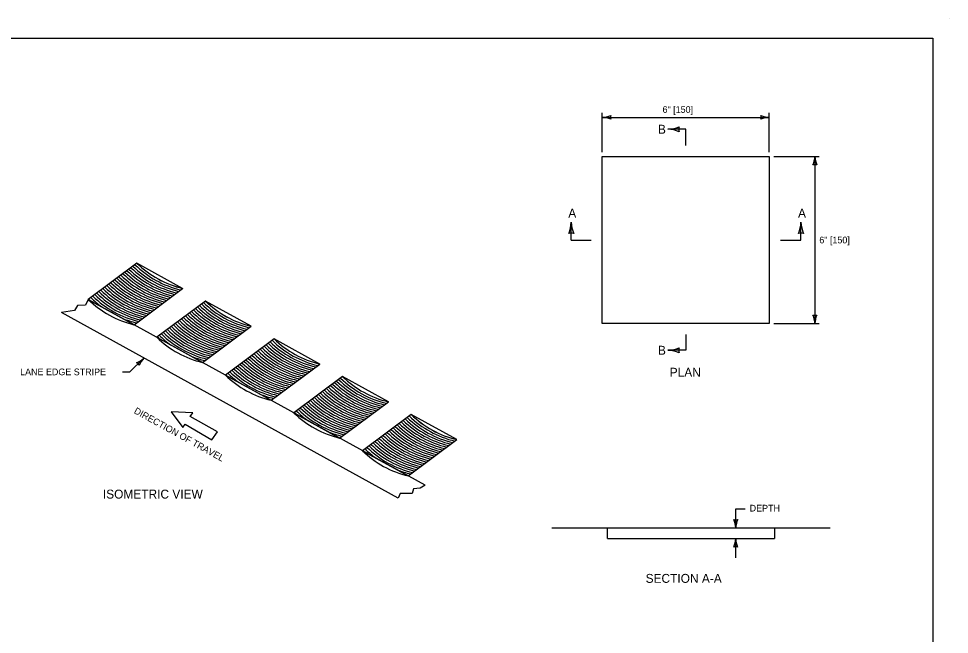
# Model space of a CAD drawing. Extents: x 49991.4 to 50021, y 49987.6 to 50011.4.
# Drawn here: x 50008.54 to 50016.9, y 49993.64 to 49999.18 of the extents above; entities that cross this region are included whole.
import ezdxf

# ---------------------------------------------------------------- set-up
doc = ezdxf.new("R2010")
doc.units = 0
for name, color, linetype in [('Level 1', 7, 'Continuous'), ('Level 2', 7, 'Continuous'), ('Level 3', 7, 'Continuous'), ('Level 4', 7, 'Continuous'), ('Level 6', 7, 'Continuous')]:
    doc.layers.add(name, color=color, linetype=linetype)

msp = doc.modelspace()

# ---------------------------------------------------------------- linework, layer by layer
at = {"layer": 'Level 1'}
for p, q in [((50016.9001, 49999.1756), (50016.9001, 49999.1756)), ((50013.7827, 49996.4368), (50013.7827, 49997.9368)), ((50013.7827, 49997.9368), (50015.2827, 49997.9368)), ((50015.2827, 49997.9368), (50015.2827, 49996.4368)), ((50010.013, 49996.752), (50009.6026, 49996.9783)), ((50009.1656, 49996.6527), (50009.139, 49996.6009)), ((50012.19, 49994.9848), (50009.1656, 49996.6527)), ((50009.0686, 49996.5998), (50009.0413, 49996.5528)), ((50009.139, 49996.6009), (50009.0686, 49996.5998)), ((50010.6291, 49996.4127), (50010.2185, 49996.639)), ((50009.0413, 49996.5528), (50008.9234, 49996.5356)), ((50011.9479, 49994.8676), (50008.9234, 49996.5356)), ((50015.2827, 49996.4368), (50013.7827, 49996.4368)), ((50011.2448, 49996.0731), (50010.8343, 49996.2995)), ((50011.8606, 49995.7335), (50011.4501, 49995.9599)), ((50010.1032, 49995.6332), (50009.9091, 49995.6438)), ((50009.9091, 49995.6438), (50010.0152, 49995.5023)), ((50010.0817, 49995.6015), (50010.1032, 49995.6332)), ((50010.3247, 49995.4635), (50010.0817, 49995.6015)), ((50012.4765, 49995.3939), (50012.066, 49995.6203)), ((50010.0152, 49995.5023), (50010.0363, 49995.5335)), ((50010.0363, 49995.5335), (50010.2756, 49995.3927)), ((50010.2756, 49995.3927), (50010.3247, 49995.4635)), ((50012.19, 49994.9848), (50012.1468, 49994.9565)), ((50011.9674, 49994.9104), (50011.9479, 49994.8676)), ((50012.0758, 49994.9112), (50011.9674, 49994.9104)), ((50012.0864, 49994.9533), (50012.0758, 49994.9112)), ((50012.1468, 49994.9565), (50012.0864, 49994.9533)), ((50013.3278, 49994.6002), (50015.8278, 49994.6002)), ((50013.8278, 49994.5052), (50013.8278, 49994.6002)), ((50015.3278, 49994.6002), (50015.3278, 49994.5052)), ((50013.8278, 49994.5052), (50015.3278, 49994.5052))]:
    msp.add_line(p, q, dxfattribs=at)
msp.add_lwpolyline([(49999.3835, 49998.9992), (50016.7501, 49998.9992), (50016.7501, 49987.7988), (49999.3835, 49987.7988)], close=True, dxfattribs=at)
for points in [[(50009.6026, 49996.9783), (50009.1656, 49996.6527), (50009.576, 49996.4263), (50010.013, 49996.752)], [(50010.2185, 49996.639), (50009.7813, 49996.3132), (50010.1917, 49996.0868), (50010.629, 49996.4127)], [(50010.8343, 49996.2995), (50010.3971, 49995.9736), (50010.8075, 49995.7473), (50011.2448, 49996.0731)], [(50011.4501, 49995.9599), (50011.0129, 49995.634), (50011.4233, 49995.4078), (50011.8606, 49995.7336)], [(50012.0659, 49995.6203), (50011.6287, 49995.2944), (50012.0391, 49995.0682), (50012.4764, 49995.394)]]:
    msp.add_lwpolyline(points, dxfattribs=at)
for centre, radius, start, end in [((50010.1267, 49997.5396), 0.8786, 225.65169, 256.59236), ((50010.1448, 49997.553), 0.8786, 225.65168, 256.59229), ((50010.1628, 49997.5665), 0.8786, 225.65167, 256.59222), ((50010.1809, 49997.5799), 0.8786, 225.65166, 256.59216), ((50010.1989, 49997.5934), 0.8786, 225.65165, 256.59209), ((50010.2166, 49997.6066), 0.8786, 225.65548, 256.59848), ((50010.217, 49997.6068), 0.8786, 225.65164, 256.59202), ((50010.0005, 49997.4455), 0.8786, 225.65176, 256.59284), ((50010.0185, 49997.4589), 0.8786, 225.65175, 256.59277), ((50010.0365, 49997.4724), 0.8786, 225.65174, 256.5927), ((50010.0546, 49997.4858), 0.8786, 225.65173, 256.59264), ((50010.0726, 49997.4992), 0.8786, 225.65172, 256.59257), ((50010.0907, 49997.5127), 0.8786, 225.65171, 256.5925), ((50010.1087, 49997.5261), 0.8786, 225.6517, 256.59243), ((50009.8922, 49997.3648), 0.8786, 225.65182, 256.59325), ((50009.9103, 49997.3782), 0.8786, 225.65181, 256.59318), ((50009.9283, 49997.3917), 0.8786, 225.6518, 256.59311), ((50009.9463, 49997.4051), 0.8786, 225.65179, 256.59305), ((50009.9644, 49997.4186), 0.8786, 225.65178, 256.59298), ((50009.9824, 49997.432), 0.8786, 225.65177, 256.59291), ((50009.784, 49997.2841), 0.8786, 225.65188, 226.8839), ((50009.802, 49997.2976), 0.8786, 225.65187, 234.15305), ((50009.82, 49997.311), 0.8786, 225.65186, 256.59352), ((50009.8381, 49997.3245), 0.8786, 225.65185, 256.59346), ((50009.8561, 49997.3379), 0.8786, 225.65184, 256.59339), ((50009.8742, 49997.3513), 0.8786, 225.65183, 256.59332), ((50010.7425, 49997.2001), 0.8786, 225.64839, 256.59124), ((50010.7605, 49997.2135), 0.8786, 225.64838, 256.59134), ((50010.7786, 49997.2269), 0.8786, 225.64837, 256.59143), ((50010.7966, 49997.2404), 0.8786, 225.64836, 256.59153), ((50010.8147, 49997.2538), 0.8786, 225.64835, 256.59162), ((50010.8326, 49997.2676), 0.8788, 225.66738, 256.61038), ((50010.8327, 49997.2673), 0.8786, 225.64834, 256.59172), ((50009.802, 49997.2976), 0.8786, 247.95966, 256.59359), ((50010.6343, 49997.1194), 0.8786, 225.64845, 256.59068), ((50010.6523, 49997.1328), 0.8786, 225.64844, 256.59077), ((50010.6703, 49997.1463), 0.8786, 225.64843, 256.59087), ((50010.6884, 49997.1597), 0.8786, 225.64842, 256.59096), ((50010.7064, 49997.1732), 0.8786, 225.64841, 256.59106), ((50010.7245, 49997.1866), 0.8786, 225.6484, 256.59115), ((50009.784, 49997.2841), 0.8786, 255.29464, 256.59765), ((50010.508, 49997.0253), 0.8786, 225.64852, 256.59002), ((50010.526, 49997.0387), 0.8786, 225.64851, 256.59012), ((50010.544, 49997.0522), 0.8786, 225.6485, 256.59021), ((50010.5621, 49997.0656), 0.8786, 225.64849, 256.5903), ((50010.5801, 49997.079), 0.8786, 225.64848, 256.5904), ((50010.5982, 49997.0925), 0.8786, 225.64847, 256.59049), ((50010.6162, 49997.1059), 0.8786, 225.64846, 256.59059), ((50010.3997, 49996.9446), 0.8786, 225.64858, 226.8845), ((50010.4178, 49996.958), 0.8786, 225.64857, 234.29264), ((50010.4358, 49996.9715), 0.8786, 225.64856, 256.58965), ((50010.4538, 49996.9849), 0.8786, 225.64855, 256.58974), ((50010.4719, 49996.9984), 0.8786, 225.64854, 256.58983), ((50010.4899, 49997.0118), 0.8786, 225.64853, 256.58993), ((50011.3583, 49996.8605), 0.8786, 225.6496, 256.59125), ((50011.3763, 49996.874), 0.8786, 225.64942, 256.59139), ((50011.3944, 49996.8874), 0.8786, 225.64924, 256.59154), ((50011.4124, 49996.9009), 0.8786, 225.64906, 256.59169), ((50011.4305, 49996.9143), 0.8786, 225.64888, 256.59184), ((50011.4485, 49996.9278), 0.8787, 225.65078, 256.59377), ((50011.4485, 49996.9278), 0.8786, 225.6487, 256.59199), ((50011.25, 49996.7799), 0.8786, 225.65067, 256.59035), ((50011.2681, 49996.7933), 0.8786, 225.65049, 256.5905), ((50011.2861, 49996.8067), 0.8786, 225.65031, 256.59065), ((50011.3042, 49996.8202), 0.8786, 225.65013, 256.5908), ((50011.3222, 49996.8336), 0.8786, 225.64996, 256.59095), ((50011.3402, 49996.8471), 0.8786, 225.64978, 256.5911), ((50010.4178, 49996.958), 0.8786, 247.95966, 256.58955), ((50010.3997, 49996.9446), 0.8786, 255.34824, 256.58946), ((50011.1418, 49996.6992), 0.8786, 225.65175, 256.58945), ((50011.1598, 49996.7126), 0.8786, 225.65157, 256.5896), ((50011.1779, 49996.7261), 0.8786, 225.65139, 256.58975), ((50011.1959, 49996.7395), 0.8786, 225.65121, 256.5899), ((50011.214, 49996.753), 0.8786, 225.65103, 256.59005), ((50011.232, 49996.7664), 0.8786, 225.65085, 256.5902), ((50011.0335, 49996.6185), 0.8786, 225.65283, 234.17234), ((50011.0516, 49996.632), 0.8786, 225.65265, 256.5887), ((50011.0696, 49996.6454), 0.8786, 225.65247, 256.58885), ((50011.0877, 49996.6589), 0.8786, 225.65229, 256.589), ((50011.1057, 49996.6723), 0.8786, 225.65211, 256.58915), ((50011.1238, 49996.6857), 0.8786, 225.65193, 256.5893), ((50011.0155, 49996.6051), 0.8786, 225.653, 226.8993), ((50011.9921, 49996.5344), 0.8786, 225.65206, 256.5924), ((50012.0102, 49996.5479), 0.8786, 225.65188, 256.59277), ((50012.0282, 49996.5613), 0.8786, 225.6517, 256.59314), ((50012.0463, 49996.5748), 0.8786, 225.65153, 256.5935), ((50012.0644, 49996.5883), 0.8787, 225.65078, 256.59377), ((50012.0643, 49996.5882), 0.8786, 225.65135, 256.59387), ((50011.8658, 49996.4403), 0.8786, 225.65332, 256.58983), ((50011.8839, 49996.4538), 0.8786, 225.65314, 256.59019), ((50011.9019, 49996.4672), 0.8786, 225.65296, 256.59056), ((50011.92, 49996.4806), 0.8786, 225.65278, 256.59093), ((50011.938, 49996.4941), 0.8786, 225.6526, 256.5913), ((50011.956, 49996.5075), 0.8786, 225.65242, 256.59167), ((50011.9741, 49996.521), 0.8786, 225.65224, 256.59203), ((50011.0335, 49996.6185), 0.8786, 248.08181, 256.58855), ((50011.0155, 49996.6051), 0.8786, 255.35485, 256.5884), ((50011.7576, 49996.3596), 0.8786, 225.6544, 256.58762), ((50011.7756, 49996.3731), 0.8786, 225.65422, 256.58799), ((50011.7937, 49996.3865), 0.8786, 225.65404, 256.58835), ((50011.8117, 49996.4), 0.8786, 225.65386, 256.58872), ((50011.8298, 49996.4134), 0.8786, 225.65368, 256.58909), ((50011.8478, 49996.4269), 0.8786, 225.6535, 256.58946), ((50011.6493, 49996.279), 0.8786, 225.65547, 234.18187), ((50011.6674, 49996.2924), 0.8786, 225.65529, 256.58578), ((50011.6854, 49996.3059), 0.8786, 225.65511, 256.58615), ((50011.7035, 49996.3193), 0.8786, 225.65493, 256.58652), ((50011.7215, 49996.3327), 0.8786, 225.65475, 256.58688), ((50011.7396, 49996.3462), 0.8786, 225.65457, 256.58725), ((50011.6313, 49996.2655), 0.8786, 225.65565, 226.90989), ((50012.6079, 49996.1949), 0.8786, 225.65471, 256.59581), ((50012.626, 49996.2083), 0.8786, 225.65453, 256.59618), ((50012.644, 49996.2218), 0.8786, 225.65435, 256.59655), ((50012.6621, 49996.2352), 0.8786, 225.65417, 256.59691), ((50012.6802, 49996.2486), 0.8787, 225.65078, 256.59377), ((50012.6801, 49996.2487), 0.8786, 225.65399, 256.59728), ((50012.4997, 49996.1142), 0.8786, 225.65579, 256.5936), ((50012.5177, 49996.1276), 0.8786, 225.65561, 256.59397), ((50012.5358, 49996.1411), 0.8786, 225.65543, 256.59434), ((50012.5538, 49996.1545), 0.8786, 225.65525, 256.59471), ((50012.5718, 49996.168), 0.8786, 225.65507, 256.59507), ((50012.5899, 49996.1814), 0.8786, 225.65489, 256.59544), ((50011.6493, 49996.279), 0.8786, 248.09369, 256.58541), ((50011.6313, 49996.2655), 0.8786, 255.36568, 256.58504), ((50012.3914, 49996.0335), 0.8786, 225.65686, 256.5914), ((50012.4095, 49996.047), 0.8786, 225.65668, 256.59176), ((50012.4275, 49996.0604), 0.8786, 225.6565, 256.59213), ((50012.4456, 49996.0739), 0.8786, 225.65632, 256.5925), ((50012.4636, 49996.0873), 0.8786, 225.65615, 256.59287), ((50012.4816, 49996.1008), 0.8786, 225.65597, 256.59323), ((50012.2651, 49995.9394), 0.8786, 225.65812, 234.20549), ((50012.2832, 49995.9529), 0.8786, 225.65794, 256.58919), ((50012.3012, 49995.9663), 0.8786, 225.65776, 256.58956), ((50012.3193, 49995.9798), 0.8786, 225.65758, 256.58992), ((50012.3373, 49995.9932), 0.8786, 225.6574, 256.59029), ((50012.3554, 49996.0066), 0.8786, 225.65722, 256.59066), ((50012.3734, 49996.0201), 0.8786, 225.65704, 256.59103), ((50012.2471, 49995.926), 0.8786, 225.6583, 226.92151), ((50012.2651, 49995.9394), 0.8786, 248.07008, 256.58882), ((50012.2471, 49995.926), 0.8786, 255.35405, 256.58845)]:
    msp.add_arc(centre, radius, start, end, dxfattribs=at)
at = {"layer": 'Level 3'}
for p, q in [((50013.7827, 49997.9768), (50013.7827, 49998.3286)), ((50015.2827, 49997.9768), (50015.2827, 49998.3286)), ((50013.7827, 49998.2886), (50015.2827, 49998.2886)), ((50015.3227, 49997.9368), (50015.7318, 49997.9368)), ((50015.6918, 49997.9368), (50015.6918, 49996.4368)), ((50015.3227, 49996.4368), (50015.7318, 49996.4368)), ((50009.5397, 49996.0023), (50009.6657, 49996.1262)), ((50009.4717, 49996.0023), (50009.5397, 49996.0023)), ((50014.9815, 49994.7736), (50015.0663, 49994.7736)), ((50014.9815, 49994.6002), (50014.9815, 49994.7736)), ((50014.9812, 49994.3318), (50014.9812, 49994.5052))]:
    msp.add_line(p, q, dxfattribs=at)
for centre, radius, start, end in [((50013.7712, 49998.5213), 0.233, 272.82731, 292.07716), ((50013.7735, 49998.0665), 0.2223, 67.45601, 87.63952), ((50013.9109, 49998.2886), 0.0548, 162.13882, 197.86118), ((50015.2919, 49998.5107), 0.2223, 247.45601, 267.63952), ((50015.1545, 49998.2886), 0.0548, 342.13882, 17.86118), ((50015.2942, 49998.0559), 0.233, 92.82731, 112.07716), ((50014.3568, 49998.4922), 0.3107, 272.82731, 292.07716), ((50014.3599, 49997.8857), 0.2964, 67.45601, 87.63952), ((50014.5431, 49998.1819), 0.073, 162.13882, 197.86118), ((50015.4697, 49997.946), 0.2223, 337.45601, 357.63952), ((50015.9245, 49997.9483), 0.233, 182.82731, 202.07716), ((50015.6918, 49997.8086), 0.0548, 72.13882, 107.86118), ((50013.2068, 49997.3599), 0.2964, 337.45601, 357.63952), ((50013.8133, 49997.363), 0.3107, 182.82731, 202.07716), ((50015.2705, 49997.3599), 0.2964, 337.45601, 357.63952), ((50015.877, 49997.363), 0.3107, 182.82731, 202.07716), ((50013.503, 49997.1768), 0.073, 72.13882, 107.86118), ((50015.5667, 49997.1768), 0.073, 72.13882, 107.86118), ((50015.6918, 49996.565), 0.0548, 252.13882, 287.86118), ((50015.4591, 49996.4253), 0.233, 2.82731, 22.07716), ((50015.9139, 49996.4277), 0.2223, 157.45601, 177.63952), ((50014.3568, 49996.5068), 0.3107, 272.82731, 292.07716), ((50014.3599, 49995.9003), 0.2964, 67.45601, 87.63952), ((50014.5431, 49996.1965), 0.073, 162.13882, 197.86118), ((50009.5164, 49996.291), 0.2223, 291.97454, 312.15805), ((50009.5742, 49996.0363), 0.0548, 26.65735, 62.37971), ((50009.837, 49995.9683), 0.233, 137.34584, 156.59569), ((50014.9815, 49994.7284), 0.0548, 252.13882, 287.86118), ((50014.7488, 49994.5887), 0.233, 2.82731, 22.07716), ((50015.2037, 49994.5911), 0.2223, 157.45601, 177.63952), ((50014.7591, 49994.5144), 0.2223, 337.45601, 357.63952), ((50015.2139, 49994.5167), 0.233, 182.82731, 202.07716), ((50014.9812, 49994.377), 0.0548, 72.13882, 107.86118)]:
    msp.add_arc(centre, radius, start, end, dxfattribs=at)
at = {"layer": 'Level 4'}
for centre, radius, start, end in [((50009.7797, 49997.2808), 0.8785, 225.64487, 256.58787), ((50010.3954, 49996.9413), 0.8785, 225.64487, 256.58787), ((50011.011, 49996.6018), 0.8784, 225.65558, 256.59857), ((50011.6267, 49996.2622), 0.8783, 225.66628, 256.60928), ((50012.2425, 49995.9226), 0.8783, 225.66628, 256.60928)]:
    msp.add_arc(centre, radius, start, end, dxfattribs=at)
at = {"layer": 'Level 6'}
for p, q in [((50014.5327, 49998.1819), (50014.3721, 49998.1819)), ((50014.5327, 49998.0368), (50014.5327, 49998.1819)), ((50013.503, 49997.1868), (50013.503, 49997.3477)), ((50015.5667, 49997.1868), (50015.5667, 49997.3477)), ((50013.503, 49997.1868), (50013.6827, 49997.1868)), ((50015.3827, 49997.1868), (50015.5667, 49997.1868)), ((50014.5327, 49996.3368), (50014.5327, 49996.1965)), ((50014.5327, 49996.1965), (50014.3721, 49996.1965))]:
    msp.add_line(p, q, dxfattribs=at)

# ---------------------------------------------------------------- texts
at = {"layer": 'Level 2'}
for s, height, p in [('6" [150]', 0.06, (50014.3237, 49998.3286)), ('B', 0.08, (50014.2823, 49998.1419)), ('A', 0.08, (50013.4769, 49997.3877)), ('A', 0.08, (50015.5406, 49997.3877)), ('6" [150]', 0.06, (50015.7318, 49997.1568)), ('B', 0.08, (50014.2823, 49996.1565)), ('LANE EDGE STRIPE', 0.06, (50008.5534, 49995.9723)), ('PLAN', 0.08, (50014.3879, 49995.9589)), ('ISOMETRIC VIEW', 0.08, (50009.2964, 49994.8646)), ('DEPTH', 0.06, (50015.1063, 49994.7482)), ('SECTION A-A', 0.08, (50014.1716, 49994.1075))]:
    msp.add_text(s, height=height, dxfattribs=at).set_placement(p)
msp.add_text('DIRECTION OF TRAVEL', height=0.06, rotation=331.01456, dxfattribs=at).set_placement((50009.5701, 49995.6347))

doc.saveas('drawing.dxf')
